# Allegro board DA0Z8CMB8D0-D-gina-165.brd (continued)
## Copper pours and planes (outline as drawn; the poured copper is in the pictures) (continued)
+SMDDR_VREF_DQ0 on BOTTOM (solid shape): 80.1,53.32 80.1,52.43 79.84,52.18 79.03,52.18 78.95,52.22 78.93,52.32 78.85,52.69 78.48,52.77 78.45,52.77 78.42,52.79 78.19,52.97 77.9,53.01 77.88,53.01 77.86,53.02 77.81,53.07 77.81,53.58 78.06,53.83 79.59,53.83
+SMDDR_VREF_DQ1 on TOP (solid shape): 97.75,88.25 97.75,81.39 97.49,81.14 95.21,81.14 94.95,81.39 94.95,88.5 95.08,88.63 97.37,88.63
+SMDDR_VREF_DQ1 on BOTTOM (solid shape): 96.53,84.87 96.53,84.85 96.53,82.81 96.53,82.81 96.53,82.15 95.69,81.31 95.23,81.31 95.13,81.42 95.13,84.41 95.72,85 96.4,85
+TPVDD on BOTTOM (solid shape): 94.45,51.93 94.45,50.66 94.32,50.53 92.16,50.53 92.03,50.4 92.03,49.51 91.14,48.62 89.11,48.62 88.99,48.75 88.99,50.53 89.06,50.65 89.09,50.78 89.09,51.27 89.49,51.67 89.49,52.31 89.62,52.43 93.94,52.43
+VGACORE on TOP (solid shape): 45.83,99.3 48.8,99.3 48.89,99.21 63.55,99.21 64.25,98.51 64.25,95.84 63.56,95.16 60.46,95.16 59.65,94.34 47.48,94.34 46.39,95.44 45.45,95.44 45.12,95.77 42,95.77 41.82,95.95 41.82,98.61 41.59,98.84 41.59,99.32 41.69,99.42 45.7,99.42
+VGACORE on TOP (solid shape): outline of 390 points within 37.73,114.28 48.07,134.46
+VGACORE on BOTTOM (solid shape): 50.63,100.54 50.63,99.81 51.22,99.22 56.37,99.22 56.65,98.94 65.03,98.94 65.08,98.89 65.08,95.13 64.83,94.88 62.95,94.88 62.92,94.89 62.91,94.9 62.9,94.93 62.9,97.44 62.44,97.44 62.44,94.93 62.43,94.9 62.42,94.89 62.39,94.88 61.2,94.88 60.61,94.29 56.6,94.29 56.59,94.28 47.52,94.28 46.87,94.93 51.42,94.93 51.42,97.59 50.96,97.59 50.96,94.93 46.87,94.93 46.36,95.44 45.42,95.44 45.13,95.73 42.03,95.73 41.82,95.95 41.82,98.69 42.41,99.29 45.23,99.29 45.41,99.46 45.41,100.19 45.92,100.69 50.47,100.69
+VGACORE on IN1 (solid shape): outline of 1210 points within 37.17,125.33 47.96,135.75
+VGACORE on IN2 (solid shape): outline of 8755 points within 31.71,94.09 60.64,136.13
+VGACORE on SVCC (solid shape): outline of 420 points within 21.55,90.41 64.98,136.38
+VGACORE on IN3 (solid shape): outline of 1027 points within 37.93,125.33 47.96,135.75
+WL_VDD on BOTTOM (solid shape): 219.41,73.61 221.1,73.61 221.19,73.52 221.19,71.84 220.08,70.73 220.08,69.7 221.19,68.58 221.19,66.15 220.81,65.77 219.16,65.77 218.91,66.02 218.91,67.17 217.38,68.69 219.31,68.69 219.31,68.66 219.32,68.61 219.34,68.56 219.36,68.51 219.39,68.47 219.43,68.43 219.47,68.4 219.51,68.37 219.56,68.35 219.61,68.34 219.67,68.33 219.72,68.34 219.77,68.35 219.82,68.37 219.87,68.4 219.91,68.43 219.95,68.47 219.98,68.51 220,68.56 220.02,68.61 220.02,68.66 220.02,68.72 220.02,68.77 220,68.82 219.98,68.87 219.95,68.91 219.91,68.95 219.87,68.99 219.82,69.01 219.77,69.03 219.72,69.04 219.67,69.05 219.61,69.04 219.56,69.03 219.51,69.01 219.47,68.99 219.43,68.95 219.39,68.91 219.36,68.87 219.34,68.82 219.32,68.77 219.31,68.72 219.31,68.69 217.38,68.69 217.13,68.94 217.13,70.85 217.38,71.1 217.38,73.11 220.96,73.11 220.96,73.31 219.41,73.31 219.41,73.11 217.38,73.11 217.38,73.39 217.61,73.61 219.41,73.61
+WL_VDD on BOTTOM (solid shape): outline of 243 points within 195.92,90.8 221.19,95.59
+WL_VDD on IN2 (solid shape): outline of 927 points within 218.14,71.61 228.3,94.73
ADOGND on TOP (solid shape): 249.87,22.77 249.87,22.17 250.42,21.62 250.42,21.44 250.41,21.4 250.37,21.39 247.43,21.39 247.36,21.42 247.33,21.5 247.31,21.92 247.14,22.3 247.13,22.4 247.21,22.46 248,22.61 248.74,22.91 248.76,22.91 249.73,22.91
ADOGND on TOP (solid shape): 237.84,23.02 237.88,22.94 237.88,22.61 238.35,22.15 238.36,22.12 238.36,22.09 238.29,21.87 238.27,21.64 238.26,21.61 238.24,21.59 237.62,20.74 238.1,19.8 238.12,19.79 238.12,19.76 238.12,11.75 238.12,11.72 238.1,11.71 237.63,10.77 238.24,9.92 238.26,9.9 238.27,9.87 238.59,9.08 239.37,8.75 240.29,8.75 241.12,9.13 241.41,10.09 241.48,10.12 243.24,10.12 243.37,10 243.37,9.61 243.02,9.27 242.26,9.27 241.59,8.6 239.79,8.6 236.7,9.21 236.6,12.36 236.6,19.15 236.2,21.38 237.75,23.03
ADOGND on BOTTOM (solid shape): 250.38,21.65 250.38,21.47 250.3,21.4 247.43,21.4 247.36,21.43 247.33,21.51 247.31,21.92 247.14,22.3 247.13,22.4 247.21,22.46 247.74,22.54 248.25,22.69 248.26,22.69 249.34,22.69
ADOGND on BOTTOM (solid shape): 247.83,10.12 247.9,10.08 247.93,10 247.93,9.69 248.02,9.4 248.01,9.3 247.92,9.25 244.99,9.25 243.39,7.65 242.44,7.65 242.34,7.72 242.37,7.84 242.27,8.45 241.8,8.04 241.8,8.01 241.78,7.99 241.65,7.86 241.58,7.83 241.51,7.86 241.16,7.95 240.91,7.69 240.91,7.68 240.88,7.65 240.67,7.65 240.22,8.11 239.48,8.11 238.97,8.62 238.95,8.75 239.07,8.79 239.22,8.76 239.37,8.75 240.29,8.75 241.12,9.13 241.41,10.08 241.48,10.12
ADOGND on BOTTOM (solid shape): outline of 817 points within 231.96,9.33 244.97,51.42
ADOGND on SGND (solid shape): outline of 333 points within 231.8,6.84 250.96,51.42
ADOGND on IN1 (solid shape): 249.87,22.69 249.87,22.17 250.42,21.62 250.42,21.44 250.41,21.4 250.37,21.39 247.43,21.39 247.36,21.42 247.33,21.5 247.31,21.92 247.14,22.3 247.13,22.4 247.21,22.46 248,22.61 248.74,22.91 248.76,22.91 249.65,22.91
ADOGND on IN1 (solid shape): 236.21,21.41 237.65,22.99 239.79,22.91 245,22.91 245.02,22.9 245.08,22.8 245.01,22.71 244.39,22.25 244.23,21.5 244.2,21.42 244.13,21.39 241.48,21.39 241.41,21.42 241.12,22.38 240.29,22.76 239.37,22.76 238.58,22.43 238.27,21.64 238.26,21.61 238.24,21.59 237.62,20.74 238.1,19.8 238.12,19.79 238.12,19.76 238.12,11.75 238.12,11.72 238.1,11.71 237.63,10.77 238.24,9.92 238.26,9.9 238.27,9.87 238.59,9.08 239.37,8.75 240.29,8.75 241.12,9.13 241.41,10.09 241.48,10.12 247.83,10.12 247.9,10.09 248.19,9.13 249.02,8.75 249.72,8.75 249.77,8.72 249.76,8.66 249.69,8.6 248.57,8.6 248.56,8.6 246.87,8.97 245.19,8.6 240.46,8.6 240.46,8.6 237.49,8.6 236.79,9.3 236.79,13.41 236.6,13.61 236.6,19.15 236.37,19.52 236.21,19.91
ADOGND on IN2 (solid shape): 249.33,22.66 249.36,22.66 249.38,22.64 250.38,21.65 250.38,21.47 250.3,21.4 247.43,21.4 247.36,21.43 247.33,21.51 247.34,21.68 247.33,21.85 247.34,21.93 247.41,21.97 248.4,22.2 249.31,22.65
ADOGND on IN2 (solid shape): outline of 793 points within 231.96,7.1 247.93,51.42
ADOGND on SVCC (solid shape): outline of 336 points within 231.8,6.84 244.56,51.42
ADOGND on IN3 (solid shape): 249.33,22.66 249.36,22.66 249.38,22.64 250.38,21.65 250.38,21.47 250.3,21.4 247.43,21.4 247.36,21.43 247.33,21.51 247.34,21.68 247.33,21.85 247.34,21.93 247.41,21.97 248.4,22.2 249.31,22.65
ADOGND on IN3 (solid shape): outline of 129 points within 239.23,7.1 247.98,10.12
ADOGND on IN3 (solid shape): outline of 809 points within 231.96,11.32 244.58,51.42
ADOGND on SGND1 (solid shape): outline of 334 points within 231.8,6.84 250.96,51.42
BAT-V on TOP (solid shape): 37.72,58.94 42.33,58.94 44.89,56.37 46.31,56.37 46.95,55.74 46.95,52.18 46.74,51.98 39.71,51.98 38.62,53.07 34.63,53.07 34.25,53.45 33.74,53.45 33.49,53.2 33.49,52.18 33.21,51.9 32.42,51.9 32.22,51.7 31.63,51.7 31.35,51.98 30.03,51.98 29.75,52.26 29.75,54.75 35.7,54.75 35.7,54.69 35.7,54.64 35.72,54.59 35.74,54.54 35.77,54.5 35.81,54.46 35.85,54.43 35.9,54.4 35.95,54.38 36,54.37 36.05,54.36 36.1,54.37 36.16,54.38 36.21,54.4 36.25,54.43 36.29,54.46 36.33,54.5 36.36,54.54 36.38,54.59 36.4,54.64 36.41,54.69 36.41,54.75 36.4,54.8 36.38,54.85 36.36,54.9 36.33,54.94 36.29,54.98 36.25,55.02 36.21,55.04 36.16,55.06 36.1,55.07 36.05,55.08 36,55.07 35.95,55.06 35.9,55.04 35.85,55.02 35.81,54.98 35.77,54.94 35.74,54.9 35.72,54.85 35.7,54.8 35.7,54.75 29.75,54.75 29.75,58.07 29.96,58.28 34.32,58.28 34.34,58.26 34.39,58.24 34.44,58.23 34.5,58.23 34.55,58.23 34.6,58.24 34.65,58.26 34.69,58.28 34.71,58.28 35.39,58.96 37.7,58.96
BAT-V on BOTTOM (solid shape): 33.55,57.73 33.55,53 33.11,52.56 28.15,52.56 27.77,52.94 27.77,56.88 28.03,57.13 29.55,57.13 30.4,57.99 33.29,57.99
BAT-V on BOTTOM (solid shape): outline of 108 points within 41.3,51.48 55.45,58.28
CARD_3V3 on BOTTOM (solid shape): 229.73,47.08 229.73,45.68 229.57,45.53 224.85,45.53 224.83,45.54 224.82,45.55 224.75,45.63 224.64,45.66 224.49,45.67 224.34,45.66 224.24,45.63 224.17,45.55 224.16,45.54 224.14,45.53 221.73,45.53 221.45,45.81 221.45,47.08 221.65,47.28 229.52,47.28
CCD_PWR on TOP (solid shape): 57.36,107.3 57.36,105.52 57.24,105.39 54.19,105.39 53.81,105.77 53.81,107.17 54.06,107.43 57.24,107.43
CCD_PWR on BOTTOM (solid shape): 57.26,106.41 57.26,105.52 57.11,105.37 56.78,105.37 56.68,105.27 56.68,104 56.42,104 56.42,105.15 56.18,105.15 56.18,104 55.92,104 55.92,106.27 56.19,106.54 57.13,106.54
CRTVDD5 on BOTTOM (solid shape): 110.14,168.2 110.18,168.19 110.19,168.15 110.19,165.46 110.59,165.07 110.6,165.05 110.62,164.85 110.7,164.71 110.7,162.45 110.68,162.37 110.68,162.29 110.67,162.27 110.66,162.25 110.58,162.16 110.19,162.16 109.94,162.42 109.94,164.32 109.31,164.96 109.31,168.15 109.32,168.19 109.36,168.2
CS_SW1 on TOP (solid shape): 134.19,149.1 134.66,148.62 134.72,148.62 135.18,148.17 136.08,148.17 136.33,147.91 136.33,147 136.58,146.75 139.48,146.75 139.63,146.59 139.63,144.74 139.48,144.59 136.79,144.59 136.33,145.04 134.22,145.04 133.49,145.78 133.49,147 132.9,147.58 132.9,148.7 133.36,149.16 134.12,149.16
CS_SW1 on BOTTOM (solid shape): 136.49,148.97 136.49,147.04 136.74,146.8 139.96,146.8 140.04,146.72 140.04,146.67 140.03,146.67 140.03,146.14 140.02,146.11 139.99,146.09 139.85,146.03 139.75,145.91 139.75,145.91 139.66,145.82 139.66,145.72 139.65,145.71 139.63,145.59 139.65,145.46 139.66,145.46 139.66,144.51 139.4,144.26 134.2,144.26 133.04,145.41 133.04,145.68 133.06,145.72 133.09,145.73 133.73,145.73 133.76,145.72 133.78,145.68 133.78,145.65 135.46,145.65 135.46,146.16 133.78,146.16 133.78,146.13 133.76,146.09 133.73,146.08 133.09,146.08 133.06,146.09 133.04,146.13 133.04,148.59 133.51,149.06 136.41,149.06
IVDDO on TOP (solid shape): 102.85,148.55 102.85,148.53 103.22,148.17 103.22,148.16 103.38,147.94 103.65,147.9 103.66,147.9 104.64,147.9 104.99,147.56 106.78,147.56 106.81,147.55 106.83,147.53 107.09,147.33 107.4,147.43 107.52,147.56 108.04,147.56 108.16,147.68 108.16,148.19 108.29,148.32 109.05,148.32 109.18,148.19 109.18,147.18 108.92,146.92 108.92,146.41 108.77,146.26 108.75,146.26 108.54,146.15 108.44,145.93 108.42,145.91 104.99,145.91 104.23,146.66 104.22,146.69 104.22,146.71 103.99,147.13 103.55,146.95 103.53,146.93 103.5,146.92 102.83,146.92 99.4,150.35 99.4,150.73 99.65,150.99 100.42,150.99
IVDDO_18 on TOP (solid shape): outline of 235 points within 102.96,147.05 111.59,155.05
LCD_VIN on TOP (solid shape): 51.32,105.9 51.79,105.75 52.27,105.89 52.28,105.9 52.66,105.9 52.92,105.65 52.92,102.98 52.66,102.73 51.52,102.73 51.14,103.11 51.14,103.32 51.09,103.37 51.08,103.38 51.01,103.49 50.9,103.56 50.89,103.57 50.75,103.71 50.75,105.76 50.89,105.9
LCD_VIN on BOTTOM (solid shape): 52.68,104 52.92,104 52.92,105.15 53.18,105.15 53.18,103.52 52.92,103.26 52.92,102.96 52.64,102.68 51.24,102.68 51.04,102.88 51.04,103.01 51.05,103.03 51.11,103.18 51.1,103.34 51.1,103.36 51.11,103.39 51.39,103.67 51.39,104.5 52.03,105.15 52.68,105.15
LCDVCC on TOP (solid shape): 52.79,102.22 52.79,101.84 52.54,101.58 51.77,101.58 51.52,101.33 51.52,99.98 51.52,99.96 51.5,99.94 51.47,99.9 51.43,99.85 51.27,99.68 46.31,99.68 46.19,99.81 46.19,100.53 46.37,100.72 47.79,100.72 48.03,100.95 48.03,101.27 48.85,102.09 50.25,102.09 50.63,102.47 52.54,102.47
LCDVCC on BOTTOM (solid shape): 54.68,104 54.92,104 54.92,105.15 55.18,105.15 55.18,104 55.42,104 55.42,105.15 55.68,105.15 55.68,103.65 53.44,101.4 53.39,101.37 53.35,101.32 53.23,101.2 53.17,101.2 53.17,100.95 52.92,100.69 51.3,100.69 51.14,100.85 51.14,102.16 51.46,102.47 52.47,102.47 52.48,102.48 52.54,102.48 52.55,102.49 52.62,102.49 53.5,103.36 53.88,103.36 54.42,103.9 54.42,105.15 54.68,105.15
LCDVCC_1 on TOP (solid shape): 47.84,103.11 47.84,101.56 47.48,101.21 46.44,101.21 46.31,101.07 46.24,101.07 46.24,101 45.93,100.69 45.17,100.69 44.92,100.95 44.92,101.33 45.17,101.58 45.17,102.94 45.38,102.94 45.4,102.97 45.8,103.13 45.76,103.56 45.73,103.63 45.76,103.7 46.19,104.12 46.82,104.12
LCDVCC_1 on BOTTOM (solid shape): 47.24,105.49 47.24,105.47 47.28,105.39 47.33,105.32 47.33,103.23 47.08,102.98 45.9,102.98 45.81,103.03 45.81,103.13 45.75,103.56 45.32,103.62 45.22,103.62 45.17,103.71 45.17,105.37 45.32,105.52 47.2,105.52
MCT1 on TOP (solid shape): 150.07,161.4 150.07,160.89 149.95,160.77 147.18,160.77 147.18,161.87 147.19,161.88 148.17,161.88 148.18,161.9 148.41,161.9 148.42,161.91 149.56,161.91
MCT2 on TOP (solid shape): 147.66,159.75 149.18,159.75 149.31,159.62 149.31,158.79 149.16,158.64 146.68,158.64 146.68,159.75 147.65,159.75
MCT3 on BOTTOM (solid shape): 149.31,159.37 149.31,158.73 149.18,158.61 146.8,158.61 146.67,158.73 146.67,159.04 148.19,159.04 148.19,159.37 146.67,159.37 146.67,159.74 146.69,159.77 148.91,159.77
MCT4 on BOTTOM (solid shape): 148.56,161.88 148.85,161.75 149.15,161.7 149.5,161.6 149.85,161.6 150.15,161.31 150.15,161.17 150.14,161.03 150.15,160.88 150.13,160.79 150.05,160.76 147.35,160.76 147.32,160.77 147.3,160.81 147.3,161.15 148.83,161.15 148.83,161.48 147.3,161.48 147.3,161.87 147.31,161.88
NV_PLLVDD on TOP (solid shape): outline of 106 points within 43.44,115.93 46.19,125.19
REGOUT on TOP (solid shape): 221.07,81.26 221.07,81.01 222.34,79.74 222.34,78.09 222.08,77.83 220.81,77.83 220.56,78.09 220.56,78.98 219.34,80.2 219.34,81.85 219.39,81.9 220.43,81.9
RX_DVDD18 on IN3 (solid shape): outline of 263 points within 98,146.29 110.32,157.34
SP_PLLVDD on TOP (solid shape): 43.66,124.21 43.66,124.19 44.03,123.83 44.03,120.76 44.92,119.87 44.92,117.08 44.79,116.95 43.14,116.95 43.01,117.08 43.01,117.59 43.14,117.71 43.14,121.14 42.96,121.32 42.95,121.36 42.93,121.41 42.9,121.46 42.86,121.5 42.82,121.54 42.77,121.57 42.72,121.59 42.68,121.6 42.25,122.03 42.25,122.89 43.06,122.89 43.06,122.83 43.07,122.78 43.09,122.73 43.11,122.68 43.14,122.64 43.18,122.6 43.22,122.57 43.27,122.54 43.31,122.52 43.37,122.51 43.42,122.5 43.47,122.51 43.53,122.52 43.57,122.54 43.62,122.57 43.66,122.6 43.7,122.64 43.73,122.68 43.75,122.73 43.77,122.78 43.78,122.83 43.78,122.89 43.77,122.94 43.75,122.99 43.73,123.04 43.7,123.08 43.66,123.12 43.62,123.16 43.57,123.18 43.53,123.2 43.47,123.21 43.42,123.22 43.37,123.21 43.31,123.2 43.27,123.18 43.22,123.16 43.18,123.12 43.14,123.08 43.11,123.04 43.09,122.99 43.07,122.94 43.06,122.89 42.25,122.89 42.25,125.01 42.43,125.19 42.68,125.19
SYSTEM_AGND on IN3 (solid shape): outline of 323 points within 194.37,66.76 203.03,69.07
TERM0 on TOP (solid shape): 155.79,162.54 155.79,160.26 155.41,159.88 152.23,159.88 150.96,158.61 149.82,158.61 149.69,158.73 149.69,159.75 149.44,160 149.44,160.38 149.56,160.51 150.33,160.51 152.48,162.67 152.49,162.67 155.66,162.67
TERM0 on BOTTOM (solid shape): 155.28,163.31 155.28,160.38 154.77,159.88 152.23,159.88 150.96,158.61 149.82,158.61 149.69,158.73 149.69,159.75 149.44,160 149.44,160.38 149.56,160.51 150.33,160.51 153.25,163.43 155.15,163.43
TP_PWR on TOP (solid shape): 57.24,103.87 57.24,103.49 56.98,103.23 56.3,103.23 55.97,102.9 55.97,101.18 55.82,101.04 55.82,100.17 55.71,100.06 54.57,100.06 54.19,100.44 54.19,101.71 54.82,102.35 54.82,102.85 54.83,102.87 54.83,103.45 55.51,104.12 56.98,104.12
USBPWR1 on BOTTOM (solid shape): 237.6,70.62 237.73,70.42 237.93,70.28 237.95,70.26 237.96,70.23 237.96,69.59 237.95,69.56 237.93,69.54 237.6,69.2 237.55,68.73 237.55,68.7 237.54,68.68 236.23,67.37 236.23,66.84 233.84,64.45 232.47,64.45 232.09,64.83 232.09,65.72 231.86,65.95 228.88,65.95 228.88,67.61 230.08,68.82 234.27,68.82 234.4,68.94 234.4,69.45 235.59,70.65 237.55,70.65
USBPWR1 on IN3 (solid shape): outline of 105 points within 230.21,63.48 237.96,70.72
USBPWR2 on TOP (solid shape): 243.32,113.55 243.32,111.77 242.71,111.17 240.84,111.17 240.84,113.33 241.36,113.85 243.01,113.85
USBPWR2 on TOP (solid shape): 240.19,135.74 240.58,135.61 240.99,135.56 241.98,135.56 242.23,135.58 242.48,135.63 242.51,135.63 242.53,135.62 242.66,135.49 242.66,133.97 242.4,133.71 239.86,133.71 239.48,134.1 239.48,135.37 239.86,135.75 240.18,135.75
USBPWR2 on BOTTOM (solid shape): 241,135.33 241,134.22 241.07,134.16 241.07,129.48 241.1,128.38 241.95,127.68 241.96,127.68 243.54,126.09 243.54,125.46 243.29,125.21 242.4,125.21 240.18,127.43 240.18,131.11 239.63,131.66 239.63,135.25 239.86,135.48 240.85,135.48
USBPWR2 on IN2 (solid shape): 241.51,135.21 241.51,130.82 241.23,130.54 241.23,129.76 241.03,128.53 241.95,127.68 241.96,127.68 245.83,123.81 245.83,113.14 244.2,111.52 241.99,111.52 241.64,111.87 241.64,113.78 241.89,114.03 242.4,114.03 243.67,115.3 243.67,123.94 240.18,127.43 240.18,133.55 239.63,134.1 239.63,135.37 239.86,135.59 241.13,135.59
USBPWR2 on IN3 (solid shape): 241.51,135.21 241.51,130.06 241.51,130.03 241.49,130.02 240.99,128.71 241.95,127.68 241.96,127.68 243.54,126.09 243.54,125.46 243.29,125.21 242.44,125.21 240.15,127.49 240.15,133.55 239.63,134.07 239.63,135.37 239.86,135.59 241.13,135.59
USBPWR3 on BOTTOM (solid shape): 237.27,87.74 237.27,87.06 233.66,83.45 232.37,83.45 232.03,83.11 232.03,81.7 231.19,81.7 230.67,82.23 230.67,86.56 232.99,86.56 233,86.5 233.01,86.45 233.03,86.4 233.06,86.35 233.09,86.31 233.13,86.28 233.17,86.25 233.22,86.22 233.27,86.21 233.32,86.2 233.38,86.2 233.43,86.21 233.48,86.22 233.53,86.25 233.57,86.28 233.61,86.31 233.65,86.35 233.67,86.4 233.69,86.45 233.7,86.5 233.71,86.56 233.7,86.61 233.69,86.66 233.67,86.71 233.65,86.76 233.61,86.8 233.57,86.83 233.53,86.86 233.48,86.89 233.43,86.9 233.38,86.91 233.32,86.91 233.27,86.9 233.22,86.89 233.17,86.86 233.13,86.83 233.09,86.8 233.06,86.76 233.03,86.71 233.01,86.66 233,86.61 232.99,86.56 230.67,86.56 230.67,87.03 231.12,87.49 234.78,87.49 235.29,87.99 237.02,87.99
USBPWR3 on IN3 (solid shape): 237.32,87.74 237.32,86.09 234.78,83.55 234.78,82.66 234.53,82.41 231.86,82.41 231.65,82.62 231.65,86.58 232.99,86.58 232.99,86.53 233,86.48 233.02,86.43 233.04,86.38 233.07,86.33 233.11,86.29 233.15,86.26 233.2,86.23 233.25,86.21 233.3,86.2 233.35,86.2 233.4,86.2 233.46,86.21 233.51,86.23 233.55,86.26 233.59,86.29 233.63,86.33 233.66,86.38 233.68,86.43 233.7,86.48 233.71,86.53 233.71,86.58 233.7,86.63 233.68,86.69 233.66,86.73 233.63,86.78 233.59,86.82 233.55,86.85 233.51,86.88 233.46,86.9 233.4,86.91 233.35,86.91 233.3,86.91 233.25,86.9 233.2,86.88 233.15,86.85 233.11,86.82 233.07,86.78 233.04,86.73 233.02,86.69 233,86.63 232.99,86.58 231.65,86.58 231.65,87.28 231.86,87.49 234.78,87.49 235.29,87.99 237.07,87.99
USBPWR4 on TOP (solid shape): 10.67,116.02 11.64,115.05 12.53,115.05 12.66,114.92 12.66,113.64 12.33,113.31 9.18,113.31 9.1,113.39 8.21,114.28 8.21,117.71 8.66,118.16 10.67,118.16
USBPWR4 on BOTTOM (solid shape): 11.77,114.41 11.77,113.65 10.9,112.78 8.1,112.78 8.1,113.08 9.4,113.08 9.4,113.28 8.1,113.28 8.1,113.58 9.4,113.58 9.4,113.78 8.1,113.78 8.1,114.08 9.4,114.08 9.4,114.28 8.1,114.28 8.1,114.58 9.91,114.58 9.99,114.66 11.52,114.66
VA1 on TOP (solid shape): 34.25,102.7 35.01,102.7 36.53,101.18 36.53,96.12 35.39,94.98 35.39,91.68 35.28,91.56 35.37,91.47 35.37,91.3 35.24,91.17 33.89,91.17 33.61,90.89 33.61,90.53 33.49,90.41 32.72,90.41 32.47,90.66 31.45,90.66 31.33,90.79 31.33,94.68 30.57,95.44 30.57,96.91 30.59,96.94 30.59,104.17 30.67,104.25 32.7,104.25
VA1 on BOTTOM (solid shape): 31.28,98.59 31.28,96.28 31.66,95.89 31.66,94.93 31.5,94.78 30.9,94.78 28.66,97.01 28.66,98.92 28.79,99.04 30.82,99.04
VA2 on TOP (solid shape): outline of 90 points within 36.03,86.78 41.49,95.2
VREFC_VMA1 on TOP (solid shape): outline of 90 points within 66.81,141.95 68.08,144.24
VREFC_VMA1 on TOP (solid shape): outline of 478 points within 65.16,131.92 70.11,137.89
VREFC_VMA1 on BOTTOM (solid shape): outline of 143 points within 65.03,122.65 69.22,127.6
VREFC_VMA1 on BOTTOM (solid shape): 68.21,141.74 68.21,140.22 68.2,140.2 68.19,140.19 68.05,139.95 68.19,139.71 68.2,139.7 68.21,139.67 68.21,139.43 68.2,139.41 68.08,139.28 68.05,139.12 68.07,139.06 68.11,138.97 68.11,138.94 68.1,138.92 67.77,138.59 67.74,138.58 67.71,138.59 67.34,138.58 67.27,138.22 67.28,138.21 67.28,137.79 66.73,137.25 65.41,137.25 65.29,137.38 65.29,137.63 65.41,137.76 66.56,137.76 66.94,138.14 66.94,138.16 66.95,138.18 67.01,138.34 66.96,138.51 66.94,138.54 66.94,138.96 67,139.08 67.01,139.24 67.02,139.26 67.43,139.66 67.45,139.68 67.47,139.68 67.7,139.72 67.81,139.92 67.77,140.1 67.64,140.21 67.58,140.27 67.58,140.34 67.6,140.54 67.5,140.72 67.48,140.79 67.5,140.86 67.59,141.1 67.46,141.42 67.48,141.49 67.52,141.91 67.13,142.07 67.1,142.07 67.08,142.08 66.94,142.22 66.94,142.5 67.04,142.6 67.34,142.6
VREFC_VMA3 on TOP (solid shape): outline of 136 points within 31.12,155.29 38.36,158.08
VREFC_VMA3 on BOTTOM (solid shape): outline of 95 points within 40.4,153.51 43.82,156.05
VREFC_VMA3 on BOTTOM (solid shape): outline of 121 points within 50.17,155.16 52.71,156.43
VREFD_VMA1 on IN3 (solid shape): outline of 90 points within 64.09,125.71 66.63,133.84
VREFD_VMA3 on IN2 (solid shape): outline of 153 points within 36.53,152.89 39.46,155.18
N05802 on TOP (solid shape): 49.04,61.49 49.05,61.49 49.87,60.66 52.37,60.66 52.95,60.08 52.95,58.06 52.86,57.97 49.02,57.97 48.19,57.14 45.01,57.14 44.91,57.24 44.9,57.24 42.95,59.19 42.95,61.55 43.26,61.86 43.28,61.87 43.3,61.87 48.65,61.87
N05802 on BOTTOM (solid shape): 50.68,61.15 52.66,61.15 52.87,60.94 53.3,60.94 53.55,60.69 53.55,59.29 53.3,59.04 50.12,59.04 48.2,57.12 44.5,57.12 44.45,57.08 42.96,57.08 42.57,57.46 42.57,61.78 43.41,62.62 49.21,62.62
N243495 on TOP (solid shape): 41.51,85.56 41.51,77.16 41.65,77.02 41.65,74.42 41.59,74.36 38.19,74.36 37.93,74.62 37.93,79.87 37.04,80.76 37.04,85.58 37.13,85.67 41.4,85.67
N7169591 on TOP (solid shape): 193,65.9 193,63.86 192.92,63.79 192.08,63.79 191.98,63.89 191.98,65.85 192.19,66.05 192.85,66.05
N7170291 on TOP (solid shape): 202.85,65.72 202.85,63.74 202.8,63.69 201.91,63.69 201.89,63.71 201.89,65.72 201.96,65.8 202.78,65.8
N16780395 on TOP (solid shape): 193.13,55.86 193.13,53.68 193.1,53.65 192.24,53.65 192.16,53.73 192.16,55.86 192.21,55.91 193.07,55.91
N16789557 on BOTTOM (solid shape): 139.92,47.37 139.92,40.79 139.82,40.69 136.44,40.69 136.29,40.84 136.29,43.51 135.1,44.7 134.13,44.7 134.11,44.71 134.11,44.95 134.13,44.99 134.16,45 135.1,45 135.11,45 135.11,45.19 135.1,45.2 134.16,45.2 134.13,45.21 134.11,45.25 134.11,45.45 134.13,45.48 134.16,45.5 135.1,45.5 135.11,45.5 135.11,45.69 135.1,45.7 134.16,45.7 134.13,45.71 134.11,45.75 134.11,45.98 134.13,46 135.1,46 135.63,46 137.1,47.47 139.82,47.47
N16876480 on TOP (solid shape): 190,75.29 190,73.14 189.98,73.11 189.01,73.11 188.93,73.19 188.93,75.32 188.98,75.37 189.92,75.37
N102398859 on TOP (solid shape): 214.97,69.96 218.02,69.96 218.14,69.83 218.14,67.17 217.89,66.91 214.14,66.91 213.76,67.29 213.76,68.5 213.32,68.94 213.32,70.21 213.45,70.34 214.59,70.34
N102411350 on TOP (solid shape): 81.87,157.97 81.87,157.46 81.75,157.34 73.11,157.34 72.95,157.17 72.94,157.17 72.72,156.67 73.25,156.55 73.56,156.55 73.78,156.47 74,156.55 74.29,156.55 74.51,156.47 74.73,156.55 75.23,156.55 75.45,156.47 75.67,156.55 75.98,156.55 76.07,156.5 76.17,156.47 76.18,156.47 76.54,156.12 77.63,156.12 77.83,155.91 77.83,154.72 77.71,154.59 76.67,154.59 75.37,155.89 73.21,155.89 73.19,155.92 72.27,155.92 72.25,155.91 71.97,156.19 71.97,157.97 72.12,158.12 81.72,158.12
N103095748 on TOP (solid shape): 145.96,165.72 145.96,164.65 145.84,164.21 145.88,163.77 145.84,163.32 145.96,162.89 145.96,157.63 145.84,157.19 145.88,156.75 145.85,156.58 145.84,156.4 145.83,156.37 145.65,156.19 142.58,156.19 142.45,156.32 142.45,157.08 142.71,157.34 144.54,157.34 144.83,157.63 144.83,162.89 144.51,163.21 142.85,163.21 142.83,163.23 142.83,164.36 144.35,165.88 145.8,165.88
N103095748 on BOTTOM (solid shape): 146.39,163.9 146.39,160.18 145.96,159.75 145.96,156.5 145.58,156.12 142.93,156.12 142.82,156.22 142.82,156.57 143.85,156.57 143.85,156.91 142.82,156.91 142.82,157.2 142.93,157.31 144.51,157.31 144.83,157.63 144.83,160 145.12,160.29 145.12,162.63 144.53,163.21 142.99,163.21 142.99,163.61 144.51,163.61 144.51,163.92 142.99,163.92 142.99,164.32 143.75,164.32 144.6,165.17 145.12,165.17
N107600701 on BOTTOM (solid shape): 101.81,148.32 101.81,148.04 101.8,148.01 101.78,148.01 101.65,147.89 101.59,147.73 101.58,147.71 101.43,147.56 99.78,147.56 99.4,147.18 99.4,146.54 99.27,146.41 98.89,146.41 98.76,146.54 98.76,147.05 98.51,147.3 98.51,148.19 98.76,148.45 101.69,148.45

Small or netless copper shapes (teardrops, artwork), in the pictures only: 42 on TOP, 6 on BOTTOM, 101 on IN2, 7 on IN3

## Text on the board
Ref Des/Silkscreen Bottom: DA0Z8CMB8D0 REV:D | MODEL:Z8C
User.Comments: 174.46 | 250.38 | 24.0x63.0 | 31.0x83.0 | 24.0x98.0
Ref Des/Silkscreen Top: DA0Z8CMB8D0 | REV:D
User.6: +1.5V_GFX | +VGACORE | +5V | +VCCIN | +1.35V_SUS | GND | VIN | +1.05V | +3V | +1.05V_S5 | ADOGND
User.18: GND | ADOGND
User.19: GND | ADOGND
User.45: XY-Check acute:Feb 07 01:52:15 2013 | XY-Check cline width:Dec 22 09:40:17 2012 | XY-Check hole keepout:Dec 21 16:11:21 2012 | XY-Check rotation:Feb 18 10:41:21 2013 | XY-Check txt overlap:Feb 18 10:38:27 2013 | XY-Check txt:Feb 18 10:41:39 2013 | XY-Cross plane-IN1-SGND:Dec 21 15:07:18 2012 | XY-Cross plane-IN2-SVCC:Dec 21 15:08:34 2012 | XY-Cross plane-IN3-SVCC:Dec 21 15:22:40 2012 | XY-Cross plane-TOP-SGND:Feb 07 01:55:11 2013 | XY-Dxf to pin check:Feb 07 01:35:55 2013 | XY-Mask check:Feb 07 02:03:34 2013 | XY-Norefdes:Feb 18 10:41:25 2013 | XY-Outline check:Feb 07 02:03:23 2013 | XY-Plane net check:Feb 07 02:02:49 2013 | XY-Prop check:Feb 07 01:54:52 2013 | XY-Symbol cross:Feb 07 01:43:06 2013 | XY-Via check:Feb 07 01:58:30 2013 | check acute:Dec 20 21:01:38 2012 | check rotation:Dec 25 19:04:17 2012 | check txt overlap:Dec 25 19:03:24 2012 | create plane:Dec 21 13:25:56 2012 | dxf to pin check:Dec 20 20:14:12 2012 | outline check:Dec 20 21:25:09 2012 | prop check:Dec 20 21:21:55 2012 | symbol cross:Dec 20 20:42:00 2012 | via check:Dec 20 21:23:15 2012 | FIGURE | TYPE | Oblong | Circle | SIZE | 59.0x20.0 | 59.0x24.0 | 63.0x24.0 | 67.0x24.0 | 10.0 | 12.0 | 14.0 | 22.0 | 24.0 | 28.0 | 31.0 | 35.0 | 118.0 | 138.0 | 142.0 | 157.0 | 165.0 | 30.0 | 43.0 | 47.0 | 55.0 | 63.0 | 65.0 | 150.0 | DRILL CHART: TOP to BOTTOM | ALL UNITS ARE IN MILS | PLATED | NON-PLATED | ROTATION | 0.000 | 90.000 | - | QTY | 8 | 7 | 4 | 6 | 2 | 35 | 4858 | 38 | 1014 | 19 | 104 | 15 | 22 | 12 | 1 | 3 | 6115 | TOTAL HOLES:
